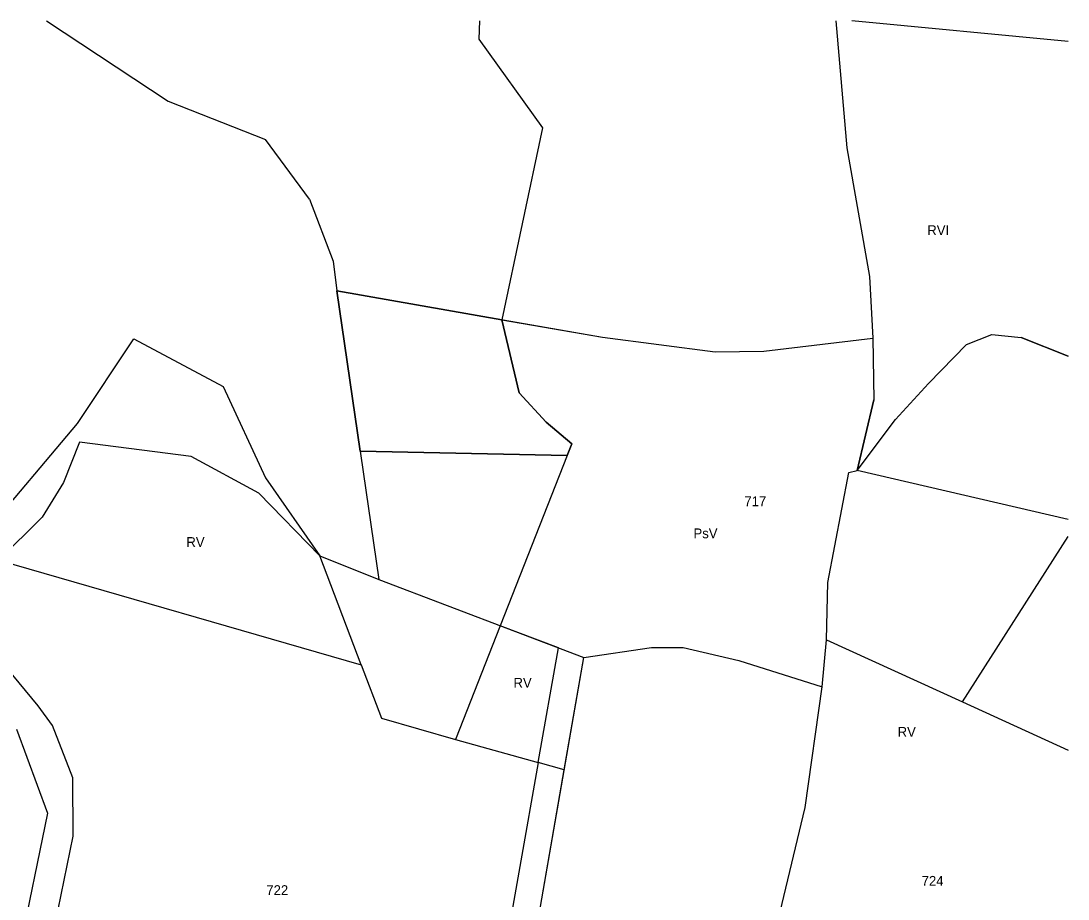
# Model space of a CAD drawing. Extents: x 7498273 to 7499989, y 5499795 to 5500810.
# Drawn here: x 7499828.5 to 7499988.9, y 5500675.1 to 5500809.6 of the extents above; entities that cross this region are included whole.
import ezdxf

# ---------------------------------------------------------------- set-up
doc = ezdxf.new("R2010")
doc.units = 0
for name, color, linetype in [('209-oznaczenie konturu klasyfikacyjnego', 7, 'Continuous'), ('211-numer działki ewidencyjnej', 7, 'Continuous'), ('217-kontur klasyfikacyjny', 7, 'Continuous'), ('218-kontur użytku gruntowego', 7, 'Continuous'), ('219-działka ewidencyjna', 7, 'Continuous')]:
    doc.layers.add(name, color=color, linetype=linetype)

msp = doc.modelspace()

# ---------------------------------------------------------------- linework, layer by layer
at = {"layer": '217-kontur klasyfikacyjny'}
for points in [[(7499898.748, 5500809.555), (7499898.67, 5500806.76)], [(7499988.876, 5500806.386), (7499955.747, 5500809.555)], [(7499898.67, 5500806.76), (7499908.38, 5500793.19)], [(7499908.38, 5500793.19), (7499902.18, 5500763.8)], [(7499880.47, 5500743.68), (7499876.91, 5500768.21)], [(7499876.91, 5500768.21), (7499902.18, 5500763.8)], [(7499902.18, 5500763.8), (7499917.57, 5500761.11)], [(7499902.18, 5500763.8), (7499904.82, 5500752.6)], [(7499917.57, 5500761.11), (7499934.85, 5500758.86)], [(7499942.3, 5500758.98), (7499958.97, 5500760.99)], [(7499958.97, 5500760.99), (7499959.12, 5500751.55)], [(7499967.52, 5500754.03), (7499973.33, 5500760.01)], [(7499973.33, 5500760.01), (7499977.21, 5500761.51)], [(7499977.21, 5500761.51), (7499981.7, 5500761.07)], [(7499981.7, 5500761.07), (7499988.876, 5500758.215)], [(7499934.85, 5500758.86), (7499942.3, 5500758.98)], [(7499962.46, 5500748.52), (7499967.52, 5500754.03)], [(7499904.82, 5500752.6), (7499908.96, 5500748.12)], [(7499959.12, 5500751.55), (7499956.59, 5500740.69)], [(7499908.96, 5500748.12), (7499912.89, 5500744.8)], [(7499956.59, 5500740.69), (7499962.46, 5500748.52)], [(7499837.5, 5500745.05), (7499835.07, 5500738.87)], [(7499854.6, 5500742.85), (7499837.5, 5500745.05)], [(7499912.89, 5500744.8), (7499912.19, 5500743.02)], [(7499864.98, 5500737.22), (7499854.6, 5500742.85)], [(7499912.19, 5500743.02), (7499880.47, 5500743.68)], [(7499912.19, 5500743.02), (7499901.92, 5500716.93)], [(7499952.11, 5500723.56), (7499955.33, 5500740.39)], [(7499955.33, 5500740.39), (7499956.59, 5500740.69)], [(7499988.876, 5500733.185), (7499956.59, 5500740.69)], [(7499835.07, 5500738.87), (7499831.76, 5500733.58)], [(7499874.32, 5500727.63), (7499864.98, 5500737.22)], [(7499831.76, 5500733.58), (7499825.08, 5500726.95)], [(7499825.08, 5500726.95), (7499880.65, 5500710.94)], [(7499880.65, 5500710.94), (7499874.32, 5500727.63)], [(7499951.91, 5500714.76), (7499952.11, 5500723.56)], [(7499901.92, 5500716.93), (7499895.06, 5500699.53)], [(7499910.86, 5500713.53), (7499901.92, 5500716.93)], [(7499831.16, 5500704.65), (7499823.35, 5500714.05)], [(7499907.75, 5500695.97), (7499910.86, 5500713.53)], [(7499914.73, 5500712.05), (7499925.08, 5500713.61)], [(7499925.08, 5500713.61), (7499929.94, 5500713.61)], [(7499929.94, 5500713.61), (7499938.46, 5500711.61)], [(7499951.21, 5500707.59), (7499951.91, 5500714.76)], [(7499911.74, 5500694.85), (7499914.73, 5500712.05)], [(7499880.65, 5500710.94), (7499883.75, 5500702.77)], [(7499938.46, 5500711.61), (7499951.21, 5500707.59)], [(7499833.37, 5500701.67), (7499831.16, 5500704.65)], [(7499883.75, 5500702.77), (7499895.06, 5500699.53)], [(7499836.46, 5500693.62), (7499833.37, 5500701.67)], [(7499895.06, 5500699.53), (7499907.75, 5500695.97)], [(7499907.75, 5500695.97), (7499896.49, 5500632.28)], [(7499911.74, 5500694.85), (7499907.75, 5500695.97)], [(7499907.64, 5500671.3), (7499911.74, 5500694.85)], [(7499836.54, 5500684.7), (7499836.46, 5500693.62)], [(7499834.23, 5500673.46), (7499836.54, 5500684.7)]]:
    msp.add_lwpolyline(points, dxfattribs=at)
at = {"layer": '218-kontur użytku gruntowego'}
for points in [[(7499898.748, 5500809.555), (7499898.67, 5500806.76)], [(7499988.876, 5500806.386), (7499955.747, 5500809.555)], [(7499898.67, 5500806.76), (7499908.38, 5500793.19)], [(7499908.38, 5500793.19), (7499902.18, 5500763.8)], [(7499876.91, 5500768.21), (7499880.47, 5500743.68)], [(7499902.18, 5500763.8), (7499876.91, 5500768.21)], [(7499904.82, 5500752.6), (7499902.18, 5500763.8)], [(7499902.18, 5500763.8), (7499917.57, 5500761.11)], [(7499917.57, 5500761.11), (7499934.85, 5500758.86)], [(7499942.3, 5500758.98), (7499958.97, 5500760.99)], [(7499958.97, 5500760.99), (7499959.12, 5500751.55)], [(7499967.52, 5500754.03), (7499973.33, 5500760.01)], [(7499973.33, 5500760.01), (7499977.21, 5500761.51)], [(7499977.21, 5500761.51), (7499981.7, 5500761.07)], [(7499981.7, 5500761.07), (7499988.876, 5500758.215)], [(7499934.85, 5500758.86), (7499942.3, 5500758.98)], [(7499962.46, 5500748.52), (7499967.52, 5500754.03)], [(7499908.96, 5500748.12), (7499904.82, 5500752.6)], [(7499959.12, 5500751.55), (7499956.59, 5500740.69)], [(7499912.89, 5500744.8), (7499908.96, 5500748.12)], [(7499956.59, 5500740.69), (7499962.46, 5500748.52)], [(7499837.5, 5500745.05), (7499835.07, 5500738.87)], [(7499854.6, 5500742.85), (7499837.5, 5500745.05)], [(7499912.19, 5500743.02), (7499912.89, 5500744.8)], [(7499864.98, 5500737.22), (7499854.6, 5500742.85)], [(7499880.47, 5500743.68), (7499912.19, 5500743.02)], [(7499912.19, 5500743.02), (7499901.92, 5500716.93)], [(7499952.11, 5500723.56), (7499955.33, 5500740.39)], [(7499955.33, 5500740.39), (7499956.59, 5500740.69)], [(7499988.876, 5500733.185), (7499956.59, 5500740.69)], [(7499835.07, 5500738.87), (7499831.76, 5500733.58)], [(7499874.32, 5500727.63), (7499864.98, 5500737.22)], [(7499831.76, 5500733.58), (7499825.08, 5500726.95)], [(7499825.08, 5500726.95), (7499880.65, 5500710.94)], [(7499880.65, 5500710.94), (7499874.32, 5500727.63)], [(7499951.91, 5500714.76), (7499952.11, 5500723.56)], [(7499901.92, 5500716.93), (7499895.06, 5500699.53)], [(7499910.86, 5500713.53), (7499901.92, 5500716.93)], [(7499831.16, 5500704.65), (7499823.35, 5500714.05)], [(7499907.75, 5500695.97), (7499910.86, 5500713.53)], [(7499914.73, 5500712.05), (7499925.08, 5500713.61)], [(7499925.08, 5500713.61), (7499929.94, 5500713.61)], [(7499929.94, 5500713.61), (7499938.46, 5500711.61)], [(7499951.21, 5500707.59), (7499951.91, 5500714.76)], [(7499911.74, 5500694.85), (7499914.73, 5500712.05)], [(7499880.65, 5500710.94), (7499883.75, 5500702.77)], [(7499938.46, 5500711.61), (7499951.21, 5500707.59)], [(7499833.37, 5500701.67), (7499831.16, 5500704.65)], [(7499883.75, 5500702.77), (7499895.06, 5500699.53)], [(7499836.46, 5500693.62), (7499833.37, 5500701.67)], [(7499895.06, 5500699.53), (7499907.75, 5500695.97)], [(7499907.75, 5500695.97), (7499896.49, 5500632.28)], [(7499911.74, 5500694.85), (7499907.75, 5500695.97)], [(7499907.64, 5500671.3), (7499911.74, 5500694.85)], [(7499836.54, 5500684.7), (7499836.46, 5500693.62)], [(7499834.23, 5500673.46), (7499836.54, 5500684.7)]]:
    msp.add_lwpolyline(points, dxfattribs=at)
at = {"layer": '219-działka ewidencyjna'}
for points in [[(7499832.424, 5500809.555), (7499851.09, 5500797.25)], [(7499953.309, 5500809.555), (7499955.02, 5500790.11)], [(7499851.09, 5500797.25), (7499866, 5500791.39)], [(7499872.74, 5500782.24), (7499866, 5500791.39)], [(7499955.02, 5500790.11), (7499958.47, 5500770.41)], [(7499872.74, 5500782.24), (7499876.34, 5500772.79)], [(7499876.34, 5500772.79), (7499876.91, 5500768.21)], [(7499958.47, 5500770.41), (7499958.97, 5500760.99)], [(7499876.91, 5500768.21), (7499917.57, 5500761.11)], [(7499876.91, 5500768.21), (7499883.33, 5500724.02)], [(7499837.22, 5500747.91), (7499845.81, 5500760.85)], [(7499845.81, 5500760.85), (7499859.5, 5500753.58)], [(7499917.57, 5500761.11), (7499934.85, 5500758.86)], [(7499942.3, 5500758.98), (7499958.97, 5500760.99)], [(7499958.97, 5500760.99), (7499959.12, 5500751.55)], [(7499967.52, 5500754.03), (7499973.33, 5500760.01)], [(7499973.33, 5500760.01), (7499977.21, 5500761.51)], [(7499977.21, 5500761.51), (7499981.7, 5500761.07)], [(7499988.876, 5500758.215), (7499981.7, 5500761.07)], [(7499934.85, 5500758.86), (7499942.3, 5500758.98)], [(7499859.5, 5500753.58), (7499865.98, 5500739.58)], [(7499962.46, 5500748.52), (7499967.52, 5500754.03)], [(7499956.59, 5500740.69), (7499959.12, 5500751.55)], [(7499822.68, 5500730.74), (7499837.22, 5500747.91)], [(7499956.59, 5500740.69), (7499962.46, 5500748.52)], [(7499865.98, 5500739.58), (7499874.32, 5500727.63)], [(7499972.73, 5500705.27), (7499988.876, 5500730.607)], [(7499874.32, 5500727.63), (7499883.33, 5500724.02)], [(7499883.33, 5500724.02), (7499914.73, 5500712.05)], [(7499914.73, 5500712.05), (7499925.08, 5500713.61)], [(7499925.08, 5500713.61), (7499929.94, 5500713.61)], [(7499929.94, 5500713.61), (7499938.46, 5500711.61)], [(7499951.21, 5500707.59), (7499951.91, 5500714.76)], [(7499951.91, 5500714.76), (7499972.73, 5500705.27)], [(7499900.9, 5500632.59), (7499914.73, 5500712.05)], [(7499938.46, 5500711.61), (7499951.21, 5500707.59)], [(7499948.6, 5500689.08), (7499951.21, 5500707.59)], [(7499972.73, 5500705.27), (7499988.876, 5500697.867)], [(7499827.83, 5500701.11), (7499832.62, 5500688.22)], [(7499832.62, 5500688.22), (7499828.25, 5500667.1)], [(7499939.46, 5500650.94), (7499948.6, 5500689.08)]]:
    msp.add_lwpolyline(points, dxfattribs=at)

# ---------------------------------------------------------------- texts
at = {"layer": '209-oznaczenie konturu klasyfikacyjnego'}
for s, p in [('RVI', (7499967.32, 5500776.76)), ('PsV', (7499931.52, 5500730.33)), ('RV', (7499853.87, 5500729)), ('RV', (7499903.96, 5500707.45)), ('RV', (7499962.78, 5500699.93))]:
    msp.add_text(s, height=1.5, dxfattribs=at).set_placement(p)
at = {"layer": '211-numer działki ewidencyjnej'}
for s, p in [('717', (7499939.31, 5500735.24)), ('724', (7499966.46, 5500677.11)), ('722', (7499866.11, 5500675.69))]:
    msp.add_text(s, height=1.5, dxfattribs=at).set_placement(p)

doc.saveas('drawing.dxf')
